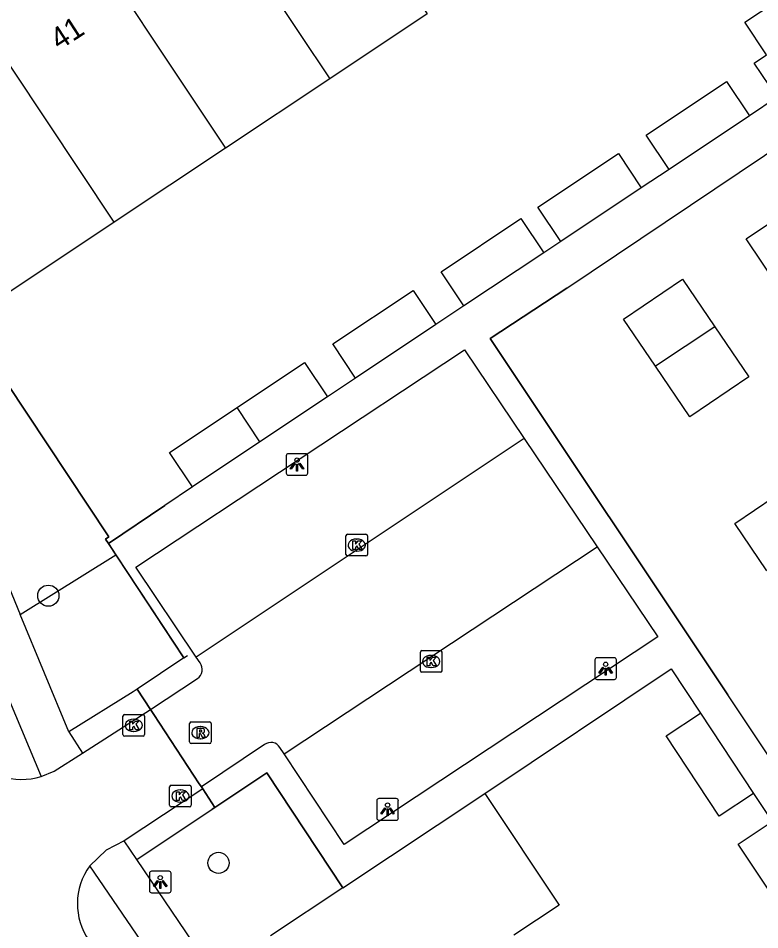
# Model space of a CAD drawing. Extents: x 158352 to 159489, y 383828 to 384597.
# Drawn here: x 158723.41 to 158757.68, y 384334.39 to 384376.52 of the extents above; entities that cross this region are included whole.
import ezdxf

# ---------------------------------------------------------------- set-up
doc = ezdxf.new("R2010")
doc.units = 0
for name, color, linetype in [('IMGEO_Boom', 7, 'Continuous'), ('IMGEO_Groenvoorziening', 7, 'Continuous'), ('IMGEO_Hek', 7, 'Continuous'), ('IMGEO_Kolk', 7, 'Continuous'), ('IMGEO_Lichtpunt', 7, 'Continuous'), ('IMGEO_Muur', 7, 'Continuous'), ('IMGEO_Pand', 7, 'Continuous'), ('IMGEO_Pand_nummerreeks', 7, 'Continuous'), ('IMGEO_Rijbaan_lokaal_open', 7, 'Continuous'), ('IMGEO_Rioolput', 7, 'Continuous'), ('IMGEO_Voetpad_gesloten', 7, 'Continuous'), ('IMGEO_Voetpad_open', 7, 'Continuous')]:
    doc.layers.add(name, color=color, linetype=linetype)

msp = doc.modelspace()

# ---------------------------------------------------------------- linework, layer by layer
at = {"layer": 'IMGEO_Boom'}
for centre in [(158724.801, 384349.824), (158732.664, 384337.476)]:
    msp.add_circle(centre, 0.489, dxfattribs=at)
at = {"layer": 'IMGEO_Groenvoorziening'}
for points in [[(158720.967, 384362.517), (158727.592, 384352.549), (158727.446, 384352.432), (158727.575, 384352.237)], [(158723.502, 384348.951), (158727.919, 384351.717)]]:
    msp.add_lwpolyline(points, dxfattribs=at)
at = {"layer": 'IMGEO_Hek'}
for points in [[(158748.765, 384364.047), (158745.221, 384361.719), (158756.206, 384345.242)], [(158729.515, 384344.573), (158728.901, 384345.506)], [(158729.669, 384344.34), (158729.515, 384344.573)], [(158731.779, 384341.137), (158729.669, 384344.34)], [(158731.872, 384340.996), (158731.779, 384341.137)], [(158731.94, 384340.893), (158731.872, 384340.996)], [(158732.501, 384340.041), (158731.94, 384340.893)]]:
    msp.add_lwpolyline(points, dxfattribs=at)
at = {"layer": 'IMGEO_Kolk'}
for p, q in [((158738.552, 384351.737), (158738.552, 384352.589)), ((158738.627, 384352.663), (158739.479, 384352.663)), ((158739.04, 384352.443), (158739.065, 384352.443)), ((158739.553, 384352.589), (158739.553, 384351.737)), ((158739.063, 384351.883), (158739.038, 384351.883)), ((158739.479, 384351.663), (158738.627, 384351.663)), ((158741.993, 384346.36), (158741.993, 384347.212)), ((158742.068, 384347.286), (158742.92, 384347.286)), ((158742.994, 384347.212), (158742.994, 384346.36)), ((158742.481, 384347.066), (158742.506, 384347.066)), ((158742.504, 384346.506), (158742.479, 384346.506)), ((158742.92, 384346.286), (158742.068, 384346.286)), ((158728.324, 384344.333), (158729.176, 384344.333)), ((158728.249, 384343.407), (158728.249, 384344.259)), ((158728.737, 384344.113), (158728.762, 384344.113)), ((158729.25, 384344.259), (158729.25, 384343.407)), ((158728.76, 384343.553), (158728.735, 384343.553)), ((158729.176, 384343.333), (158728.324, 384343.333)), ((158730.404, 384340.14), (158730.404, 384340.992)), ((158730.479, 384341.066), (158731.331, 384341.066)), ((158731.405, 384340.992), (158731.405, 384340.14)), ((158730.892, 384340.846), (158730.917, 384340.846)), ((158731.331, 384340.066), (158730.479, 384340.066)), ((158730.915, 384340.286), (158730.89, 384340.286))]:
    msp.add_line(p, q, dxfattribs=at)
for points in [[(158738.552, 384351.737), (158738.552, 384352.589)], [(158738.627, 384352.663), (158739.479, 384352.663)], [(158738.873, 384352.363), (158738.996, 384352.363), (158738.996, 384352.212), (158739.126, 384352.363), (158739.29, 384352.363), (158739.144, 384352.212), (158739.297, 384351.963), (158739.145, 384351.963), (158739.06, 384352.127), (158738.996, 384352.06), (158738.996, 384351.963), (158738.873, 384351.963), (158738.873, 384352.363)], [(158739.553, 384352.589), (158739.553, 384351.737)], [(158739.479, 384351.663), (158738.627, 384351.663)], [(158741.993, 384346.36), (158741.993, 384347.212)], [(158742.068, 384347.286), (158742.92, 384347.286)], [(158742.994, 384347.212), (158742.994, 384346.36)], [(158742.314, 384346.986), (158742.437, 384346.986), (158742.437, 384346.835), (158742.567, 384346.986), (158742.731, 384346.986), (158742.585, 384346.835), (158742.738, 384346.586), (158742.586, 384346.586), (158742.501, 384346.75), (158742.437, 384346.683), (158742.437, 384346.586), (158742.314, 384346.586), (158742.314, 384346.986)], [(158742.92, 384346.286), (158742.068, 384346.286)], [(158728.324, 384344.333), (158729.176, 384344.333)], [(158728.249, 384343.407), (158728.249, 384344.259)], [(158728.57, 384344.033), (158728.693, 384344.033), (158728.693, 384343.882), (158728.823, 384344.033), (158728.987, 384344.033), (158728.841, 384343.882), (158728.994, 384343.633), (158728.842, 384343.633), (158728.757, 384343.797), (158728.693, 384343.73), (158728.693, 384343.633), (158728.57, 384343.633), (158728.57, 384344.033)], [(158729.25, 384344.259), (158729.25, 384343.407)], [(158729.176, 384343.333), (158728.324, 384343.333)], [(158730.404, 384340.14), (158730.404, 384340.992)], [(158730.479, 384341.066), (158731.331, 384341.066)], [(158731.405, 384340.992), (158731.405, 384340.14)], [(158730.725, 384340.766), (158730.848, 384340.766), (158730.848, 384340.615), (158730.978, 384340.766), (158731.142, 384340.766), (158730.996, 384340.615), (158731.149, 384340.366), (158730.997, 384340.366), (158730.912, 384340.53), (158730.848, 384340.463), (158730.848, 384340.366), (158730.725, 384340.366), (158730.725, 384340.766)], [(158731.331, 384340.066), (158730.479, 384340.066)]]:
    msp.add_lwpolyline(points, dxfattribs=at)
for centre, start, end in [((158738.629, 384352.587), 91.552, 178.448), ((158738.629, 384352.587), 91.552, 178.448), ((158739.477, 384352.587), 1.552, 88.448), ((158739.477, 384352.587), 1.552, 88.448), ((158738.629, 384351.739), 181.552, 268.448), ((158738.629, 384351.739), 181.552, 268.448), ((158739.477, 384351.739), 271.552, 358.448), ((158739.477, 384351.739), 271.552, 358.448), ((158742.07, 384347.21), 91.552, 178.448), ((158742.07, 384347.21), 91.552, 178.448), ((158742.918, 384347.21), 1.552, 88.448), ((158742.918, 384347.21), 1.552, 88.448), ((158742.07, 384346.362), 181.552, 268.448), ((158742.07, 384346.362), 181.552, 268.448), ((158742.918, 384346.362), 271.552, 358.448), ((158742.918, 384346.362), 271.552, 358.448), ((158728.326, 384344.257), 91.552, 178.448), ((158728.326, 384344.257), 91.552, 178.448), ((158729.174, 384344.257), 1.552, 88.448), ((158729.174, 384344.257), 1.552, 88.448), ((158728.326, 384343.409), 181.552, 268.448), ((158728.326, 384343.409), 181.552, 268.448), ((158729.174, 384343.409), 271.552, 358.448), ((158729.174, 384343.409), 271.552, 358.448), ((158730.481, 384340.99), 91.552, 178.448), ((158730.481, 384340.99), 91.552, 178.448), ((158731.329, 384340.99), 1.552, 88.448), ((158731.329, 384340.99), 1.552, 88.448), ((158730.481, 384340.142), 181.552, 268.448), ((158730.481, 384340.142), 181.552, 268.448), ((158731.329, 384340.142), 271.552, 358.448), ((158731.329, 384340.142), 271.552, 358.448)]:
    msp.add_arc(centre, 0.0765, start, end, dxfattribs=at)
for centre, major_axis, ratio, start_param, end_param in [((158739.039, 384352.163), (-0.387, 0.002), 0.722429, 4.712389, 7.853982), ((158739.064, 384352.163), (-0.39, 0.002), 0.717154, 1.570796, 4.712389), ((158742.48, 384346.786), (-0.387, 0.002), 0.722429, 4.712389, 7.853982), ((158742.505, 384346.786), (-0.39, 0.002), 0.717154, 1.570796, 4.712389), ((158728.736, 384343.833), (-0.387, 0.002), 0.722429, 4.712389, 7.853982), ((158728.761, 384343.833), (-0.39, 0.002), 0.717154, 1.570796, 4.712389), ((158730.891, 384340.566), (-0.387, 0.002), 0.722429, 4.712389, 7.853982), ((158730.916, 384340.566), (-0.39, 0.002), 0.717154, 1.570796, 4.712389)]:
    msp.add_ellipse(centre, major_axis=major_axis, ratio=ratio, start_param=start_param, end_param=end_param, dxfattribs=at)
at = {"layer": 'IMGEO_Lichtpunt'}
for p, q in [((158735.795, 384356.295), (158735.795, 384355.488)), ((158735.795, 384356.295), (158735.795, 384355.488)), ((158736.697, 384356.39), (158735.889, 384356.39)), ((158736.697, 384356.39), (158735.889, 384356.39)), ((158736.791, 384355.488), (158736.791, 384356.295)), ((158736.791, 384355.488), (158736.791, 384356.295)), ((158735.889, 384355.394), (158736.697, 384355.394)), ((158735.889, 384355.394), (158736.697, 384355.394)), ((158750.059, 384346.859), (158750.059, 384346.052)), ((158750.059, 384346.859), (158750.059, 384346.052)), ((158750.961, 384346.954), (158750.153, 384346.954)), ((158750.961, 384346.954), (158750.153, 384346.954)), ((158751.055, 384346.052), (158751.055, 384346.859)), ((158751.055, 384346.052), (158751.055, 384346.859)), ((158750.153, 384345.958), (158750.961, 384345.958)), ((158750.153, 384345.958), (158750.961, 384345.958)), ((158739.98, 384340.352), (158739.98, 384339.545)), ((158739.98, 384340.352), (158739.98, 384339.545)), ((158740.882, 384340.447), (158740.074, 384340.447)), ((158740.882, 384340.447), (158740.074, 384340.447)), ((158740.976, 384339.545), (158740.976, 384340.352)), ((158740.976, 384339.545), (158740.976, 384340.352)), ((158740.074, 384339.451), (158740.882, 384339.451)), ((158740.074, 384339.451), (158740.882, 384339.451)), ((158729.476, 384336.995), (158729.476, 384336.188)), ((158729.476, 384336.995), (158729.476, 384336.188)), ((158730.378, 384337.09), (158729.57, 384337.09)), ((158730.378, 384337.09), (158729.57, 384337.09)), ((158730.472, 384336.188), (158730.472, 384336.995)), ((158730.472, 384336.188), (158730.472, 384336.995)), ((158729.57, 384336.094), (158730.378, 384336.094)), ((158729.57, 384336.094), (158730.378, 384336.094))]:
    msp.add_line(p, q, dxfattribs=at)
for points in [[(158736.169, 384355.959), (158736.208, 384355.931), (158736.02, 384355.669), (158735.982, 384355.696), (158736.169, 384355.959)], [(158736.271, 384355.911), (158736.318, 384355.911), (158736.318, 384355.589), (158736.271, 384355.589), (158736.271, 384355.911)], [(158736.381, 384355.931), (158736.419, 384355.958), (158736.606, 384355.696), (158736.567, 384355.668), (158736.381, 384355.931)], [(158750.433, 384346.523), (158750.472, 384346.495), (158750.284, 384346.233), (158750.246, 384346.26), (158750.433, 384346.523)], [(158750.535, 384346.475), (158750.582, 384346.475), (158750.582, 384346.153), (158750.535, 384346.153), (158750.535, 384346.475)], [(158750.645, 384346.495), (158750.683, 384346.522), (158750.87, 384346.26), (158750.831, 384346.232), (158750.645, 384346.495)], [(158740.354, 384340.016), (158740.393, 384339.988), (158740.205, 384339.726), (158740.167, 384339.753), (158740.354, 384340.016)], [(158740.456, 384339.968), (158740.503, 384339.968), (158740.503, 384339.646), (158740.456, 384339.646), (158740.456, 384339.968)], [(158740.566, 384339.988), (158740.604, 384340.015), (158740.791, 384339.753), (158740.752, 384339.725), (158740.566, 384339.988)], [(158729.85, 384336.659), (158729.889, 384336.631), (158729.701, 384336.369), (158729.663, 384336.396), (158729.85, 384336.659)], [(158729.952, 384336.611), (158729.999, 384336.611), (158729.999, 384336.289), (158729.952, 384336.289), (158729.952, 384336.611)], [(158730.062, 384336.631), (158730.1, 384336.658), (158730.287, 384336.396), (158730.248, 384336.368), (158730.062, 384336.631)]]:
    msp.add_lwpolyline(points, dxfattribs=at)
for centre in [(158736.294, 384356.093), (158750.558, 384346.657), (158740.479, 384340.15), (158729.975, 384336.793)]:
    msp.add_circle(centre, 0.0994, dxfattribs=at)
for centre, start, end in [((158735.889, 384356.295), 90, 180), ((158735.889, 384356.295), 90, 180), ((158736.697, 384356.295), 0, 90), ((158736.697, 384356.295), 0, 90), ((158735.889, 384355.488), 180, 270), ((158735.889, 384355.488), 180, 270), ((158736.697, 384355.488), 270, 0), ((158736.697, 384355.488), 270, 360), ((158750.153, 384346.859), 90, 180), ((158750.153, 384346.859), 90, 180), ((158750.961, 384346.859), 0, 90), ((158750.961, 384346.859), 0, 90), ((158750.153, 384346.052), 180, 270), ((158750.153, 384346.052), 180, 270), ((158750.961, 384346.052), 270, 0), ((158750.961, 384346.052), 270, 360), ((158740.074, 384340.352), 90, 180), ((158740.074, 384340.352), 90, 180), ((158740.882, 384340.352), 0, 90), ((158740.882, 384340.352), 0, 90), ((158740.074, 384339.545), 180, 270), ((158740.074, 384339.545), 180, 270), ((158740.882, 384339.545), 270, 0), ((158740.882, 384339.545), 270, 360), ((158729.57, 384336.995), 90, 180), ((158729.57, 384336.995), 90, 180), ((158730.378, 384336.995), 0, 90), ((158730.378, 384336.995), 0, 90), ((158729.57, 384336.188), 180, 270), ((158729.57, 384336.188), 180, 270), ((158730.378, 384336.188), 270, 0), ((158730.378, 384336.188), 270, 360)]:
    msp.add_arc(centre, 0.0946, start, end, dxfattribs=at)
at = {"layer": 'IMGEO_Muur'}
for points in [[(158727.575, 384352.237), (158727.446, 384352.432), (158727.592, 384352.549), (158720.967, 384362.517)], [(158727.575, 384352.237), (158730.179, 384353.993)], [(158731.062, 384346.956), (158727.575, 384352.237)], [(158731.062, 384346.956), (158728.901, 384345.506)], [(158731.062, 384346.956), (158731.231, 384347.069)], [(158728.901, 384345.506), (158728.727, 384345.389)], [(158738.413, 384336.326), (158734.896, 384341.645), (158732.501, 384340.041)], [(158732.501, 384340.041), (158732.368, 384339.952)]]:
    msp.add_lwpolyline(points, dxfattribs=at)
at = {"layer": 'IMGEO_Pand'}
for points in [[(158731.523, 384383.135), (158736.414, 384375.806), (158737.806, 384373.72)], [(158726.714, 384379.933), (158731.6, 384372.593), (158732.988, 384370.513)], [(158758.483, 384372.862), (158757.425, 384374.44), (158757.998, 384374.824), (158756.989, 384376.327), (158762.145, 384379.758), (158764.201, 384376.698)], [(158740.91, 384378.806), (158742.306, 384376.714), (158737.806, 384373.72)], [(158727.843, 384367.089), (158721.573, 384376.51)], [(158737.806, 384373.72), (158732.988, 384370.513)], [(158753.487, 384369.532), (158752.432, 384371.112), (158756.146, 384373.592), (158757.201, 384372.012)], [(158757.201, 384372.012), (158753.487, 384369.532)], [(158758.593, 384364.018), (158757.051, 384366.326), (158760.534, 384368.651), (158759.083, 384370.824), (158759.016, 384370.924)], [(158732.988, 384370.513), (158727.843, 384367.089)], [(158748.481, 384366.203), (158747.429, 384367.785), (158751.148, 384370.26), (158752.201, 384368.678)], [(158752.201, 384368.678), (158748.481, 384366.203)], [(158727.843, 384367.089), (158720.967, 384362.517)], [(158744.007, 384363.216), (158742.954, 384364.797), (158746.643, 384367.255), (158747.696, 384365.674)], [(158747.696, 384365.674), (158744.007, 384363.216)], [(158752.861, 384360.428), (158751.381, 384362.606), (158754.102, 384364.455), (158755.597, 384362.255)], [(158738.996, 384359.881), (158737.942, 384361.462), (158741.657, 384363.937), (158742.711, 384362.356)], [(158742.711, 384362.356), (158738.996, 384359.881)], [(158755.597, 384362.255), (158752.861, 384360.428)], [(158755.597, 384362.255), (158757.172, 384359.937), (158754.451, 384358.088), (158752.861, 384360.428)], [(158733.526, 384358.521), (158736.647, 384360.602), (158737.701, 384359.021)], [(158737.701, 384359.021), (158734.58, 384356.94)], [(158731.459, 384354.86), (158730.405, 384356.441), (158733.526, 384358.521)], [(158734.58, 384356.94), (158733.526, 384358.521)], [(158734.58, 384356.94), (158731.459, 384354.86)], [(158758.007, 384350.981), (158756.527, 384353.159), (158759.248, 384355.008), (158760.743, 384352.808)], [(158757.396, 384340.69), (158755.811, 384339.642), (158753.357, 384343.35), (158754.941, 384344.399)], [(158754.941, 384344.399), (158757.396, 384340.69)], [(158738.413, 384336.326), (158744.975, 384340.685)], [(158744.975, 384340.685), (158748.402, 384335.525), (158746.317, 384334.13)], [(158760.724, 384335.696), (158759.144, 384334.64), (158756.675, 384338.335), (158758.255, 384339.391)], [(158738.413, 384336.326), (158735.061, 384334.1)]]:
    msp.add_lwpolyline(points, dxfattribs=at)
at = {"layer": 'IMGEO_Rijbaan_lokaal_open'}
for points in [[(158746.789, 384357.096), (158731.631, 384346.992)], [(158746.789, 384357.096), (158750.161, 384352.085)], [(158735.694, 384342.523), (158750.161, 384352.085)], [(158731.813, 384346.722), (158731.631, 384346.992)], [(158729.515, 384344.573), (158731.691, 384345.995)], [(158726.374, 384342.546), (158729.515, 384344.573)], [(158729.515, 384344.573), (158729.669, 384344.34), (158731.779, 384341.137), (158731.872, 384340.996)], [(158734.792, 384342.944), (158731.872, 384340.996)], [(158735.694, 384342.523), (158735.506, 384342.806)], [(158724.469, 384341.47), (158725.076, 384341.719), (158726.374, 384342.546)], [(158731.94, 384340.893), (158728.305, 384338.489)], [(158731.872, 384340.996), (158731.94, 384340.893)], [(158728.305, 384338.489), (158727.478, 384338.067), (158726.711, 384337.334)]]:
    msp.add_lwpolyline(points, dxfattribs=at)
for centre, radius, start, end in [((158731.4, 384346.418), 0.513, 304.568, 36.3796), ((158735.088, 384342.56), 0.485, 30.5179, 127.6039), ((158723.552, 384344.574), 3.237, 220.2193, 286.466), ((158729.114, 384335.585), 2.972, 143.9473, 214.8223)]:
    msp.add_arc(centre, radius, start, end, dxfattribs=at)
at = {"layer": 'IMGEO_Rioolput'}
for p, q in [((158731.327, 384343.068), (158731.327, 384343.92)), ((158731.402, 384343.994), (158732.254, 384343.994)), ((158732.328, 384343.92), (158732.328, 384343.068)), ((158731.815, 384343.774), (158731.84, 384343.774)), ((158731.838, 384343.214), (158731.813, 384343.214)), ((158732.254, 384342.994), (158731.402, 384342.994))]:
    msp.add_line(p, q, dxfattribs=at)
for points in [[(158731.327, 384343.068), (158731.327, 384343.92)], [(158731.402, 384343.994), (158732.254, 384343.994)], [(158732.328, 384343.92), (158732.328, 384343.068)], [(158731.916, 384343.692), (158731.664, 384343.694), (158731.664, 384343.294)], [(158731.664, 384343.294), (158731.788, 384343.294), (158731.788, 384343.456), (158731.799, 384343.456)], [(158731.842, 384343.613), (158731.788, 384343.613), (158731.788, 384343.532)], [(158731.788, 384343.532), (158731.84, 384343.532)], [(158731.846, 384343.427), (158731.917, 384343.294), (158732.057, 384343.294), (158731.992, 384343.42)], [(158732.254, 384342.994), (158731.402, 384342.994)]]:
    msp.add_lwpolyline(points, dxfattribs=at)
for centre, radius, start, end in [((158731.404, 384343.918), 0.0765, 91.552, 178.448), ((158731.404, 384343.918), 0.0765, 91.552, 178.448), ((158732.252, 384343.918), 0.0765, 1.552, 88.448), ((158732.252, 384343.918), 0.0765, 1.552, 88.448), ((158731.798, 384343.403), 0.0533, 26.0293, 88.6989), ((158731.824, 384343.721), 0.19, 274.7715, 282.9687), ((158731.848, 384343.517), 0.0964, 77.0061, 93.1865), ((158731.862, 384343.574), 0.0378, 276.6634, 79.6772), ((158731.915, 384343.582), 0.109, 350.3612, 89.416), ((158731.913, 384343.582), 0.112, 277.5842, 350.9817), ((158731.897, 384343.367), 0.108, 29.5134, 73.7905), ((158731.404, 384343.07), 0.0765, 181.552, 268.448), ((158731.404, 384343.07), 0.0765, 181.552, 268.448), ((158732.252, 384343.07), 0.0765, 271.552, 358.448), ((158732.252, 384343.07), 0.0765, 271.552, 358.448)]:
    msp.add_arc(centre, radius, start, end, dxfattribs=at)
for centre, major_axis, ratio, start_param, end_param in [((158731.814, 384343.494), (-0.387, 0.002), 0.722429, 4.712389, 7.853982), ((158731.839, 384343.494), (-0.39, 0.002), 0.717154, 1.570796, 4.712389)]:
    msp.add_ellipse(centre, major_axis=major_axis, ratio=ratio, start_param=start_param, end_param=end_param, dxfattribs=at)
at = {"layer": 'IMGEO_Voetpad_gesloten'}
for points in [[(158721.602, 384353.545), (158723.502, 384348.951)], [(158719.789, 384352.617), (158724.469, 384341.47)], [(158725.745, 384343.528), (158723.502, 384348.951)], [(158725.745, 384343.528), (158726.374, 384342.546)], [(158728.888, 384337.629), (158728.305, 384338.489)], [(158732.447, 384332.379), (158728.888, 384337.629)], [(158730.838, 384331.32), (158726.711, 384337.334)]]:
    msp.add_lwpolyline(points, dxfattribs=at)
at = {"layer": 'IMGEO_Voetpad_open'}
for points in [[(158758.483, 384372.862), (158757.201, 384372.012)], [(158776.252, 384343.646), (158763.113, 384334.884), (158756.206, 384345.242), (158745.221, 384361.719), (158748.765, 384364.047), (158759.016, 384370.924)], [(158753.487, 384369.532), (158752.201, 384368.678)], [(158748.481, 384366.203), (158747.696, 384365.674)], [(158744.007, 384363.216), (158742.711, 384362.356)], [(158731.631, 384346.992), (158728.838, 384351.146), (158744.034, 384361.191), (158746.789, 384357.096)], [(158738.996, 384359.881), (158737.701, 384359.021)], [(158731.459, 384354.86), (158730.179, 384353.993), (158727.575, 384352.237)], [(158727.575, 384352.237), (158727.919, 384351.717)], [(158750.161, 384352.085), (158752.962, 384347.923), (158738.477, 384338.328), (158735.694, 384342.523)], [(158727.919, 384351.717), (158731.062, 384346.956), (158728.901, 384345.506)], [(158744.975, 384340.685), (158753.588, 384346.445), (158754.941, 384344.399)], [(158728.901, 384345.506), (158728.727, 384345.389), (158725.745, 384343.528)], [(158728.901, 384345.506), (158729.515, 384344.573)], [(158732.501, 384340.041), (158734.896, 384341.645), (158738.413, 384336.326)], [(158731.94, 384340.893), (158732.501, 384340.041)], [(158757.396, 384340.69), (158758.255, 384339.391)], [(158728.888, 384337.629), (158732.368, 384339.952), (158732.501, 384340.041)]]:
    msp.add_lwpolyline(points, dxfattribs=at)

# ---------------------------------------------------------------- texts
at = {"layer": 'IMGEO_Pand_nummerreeks'}
msp.add_text('41', height=1, rotation=33.0302, dxfattribs=at).set_placement((158725.302, 384375.013))

doc.saveas('drawing.dxf')
